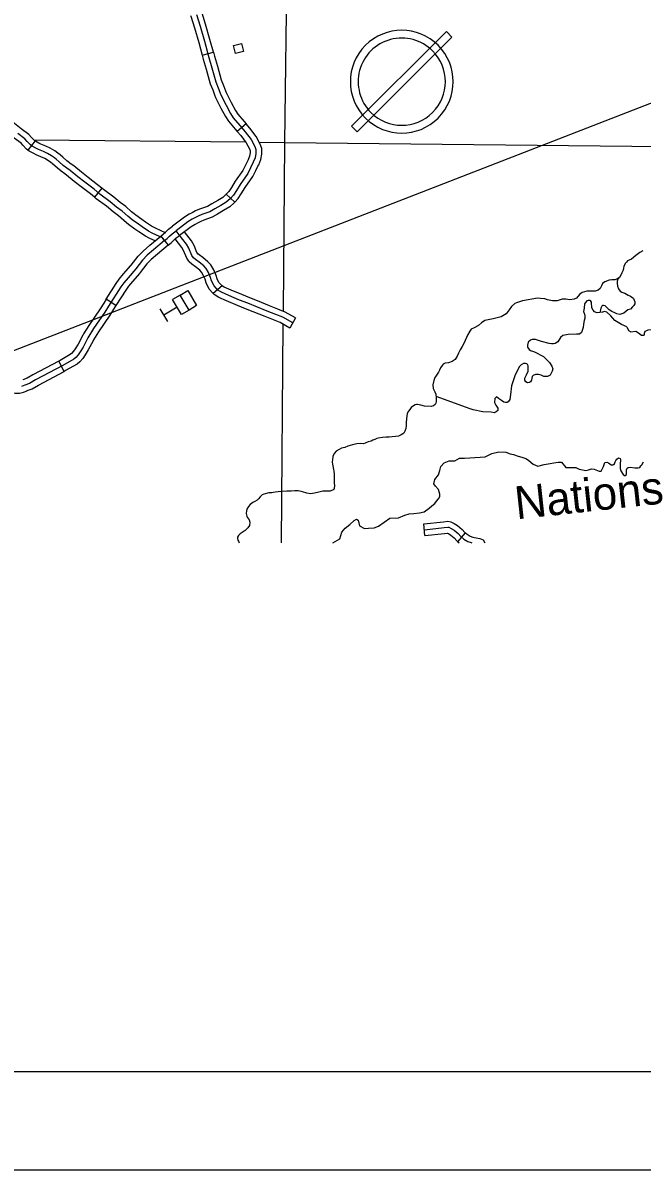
# Model space of a CAD drawing. Extents: x 61396 to 64680, y 55472 to 57605.
# Drawn here: x 62177.9 to 62426.4, y 55472.1 to 55932.3 of the extents above; entities that cross this region are included whole.
import ezdxf

# ---------------------------------------------------------------- set-up
doc = ezdxf.new("R2010")
doc.units = 0
for name, color, linetype in [('31', 7, 'Continuous'), ('32', 7, 'Continuous'), ('35', 7, 'Continuous'), ('45', 7, 'Continuous'), ('5', 7, 'Continuous'), ('56', 7, 'Continuous'), ('57', 7, 'Continuous'), ('Default', 7, 'Continuous'), ('R_No Plot', 7, 'Continuous')]:
    doc.layers.add(name, color=color, linetype=linetype)

msp = doc.modelspace()

# ---------------------------------------------------------------- linework, layer by layer
at = {"layer": '31'}
for p, q in [((62249.85, 55919.35), (62254.37, 55920.6)), ((62267.47, 55891.85), (62263.92, 55888.79)), ((62259.51, 55863.54), (62263, 55860.41)), ((62233.2, 55846.77), (62236.22, 55843.19)), ((62224.76, 55831.97), (62224.76, 55831.97)), ((62215.23, 55818.91), (62211.28, 55821.44)), ((62194.48, 55792.51), (62192.29, 55796.66)), ((62179.64, 55784.79), (62179.64, 55784.79))]:
    msp.add_line(p, q, dxfattribs=at)
for points in [[(62247.51, 55935.61), (62248.99, 55931.05), (62250.73, 55925.01), (62252.56, 55918.36), (62253.69, 55914.31), (62255.28, 55908.63), (62256.26, 55906.29), (62257.35, 55903.38), (62259.45, 55899.25), (62261.24, 55895.98), (62262.33, 55894.27), (62264.93, 55891.2), (62267.15, 55888.63), (62269.49, 55885.51), (62271.01, 55882.75), (62271.43, 55881.51), (62271.43, 55879.91), (62271.08, 55878.16), (62270.38, 55876.37), (62269.29, 55874.19), (62268.16, 55871.9), (62265.09, 55867.54), (62263.57, 55865.01), (62262.4, 55863.26), (62261.04, 55861.74), (62259.52, 55860.38), (62257.27, 55859.02), (62254.89, 55857.65), (62252.91, 55856.56), (62249.68, 55855.4), (62248.24, 55854.77), (62245.83, 55853.53), (62244.11, 55852.44), (62239.36, 55848.92)], [(62245.17, 55935.33), (62245.24, 55935.01), (62246.75, 55930.36), (62248.47, 55924.37), (62249.85, 55919.35)], [(62254.37, 55920.6), (62252.98, 55925.64), (62251.24, 55931.74), (62249.78, 55936.21), (62249.77, 55936.27)], [(62254.37, 55920.6), (62254.82, 55918.98), (62255.94, 55914.94), (62257.5, 55909.4), (62258.44, 55907.15), (62259.22, 55905.06)], [(62249.85, 55919.35), (62250.3, 55917.73), (62251.43, 55913.68), (62253.06, 55907.86), (62254.08, 55905.43), (62254.83, 55903.42)], [(62254.83, 55903.42), (62255.2, 55902.43), (62257.37, 55898.16), (62259.22, 55894.79), (62260.44, 55892.88), (62263.15, 55889.67), (62263.92, 55888.79)], [(62259.22, 55905.06), (62259.49, 55904.32), (62261.52, 55900.35), (62263.26, 55897.18), (62264.22, 55895.66), (62266.71, 55892.72), (62267.47, 55891.85)], [(62263.92, 55888.79), (62265.33, 55887.16), (62267.51, 55884.24), (62268.85, 55881.8), (62269.09, 55881.12), (62269.09, 55880.14), (62268.83, 55878.82), (62268.24, 55877.32), (62268.02, 55876.88)], [(62272.21, 55874.78), (62272.53, 55875.42), (62273.34, 55877.5), (62273.78, 55879.68), (62273.78, 55881.9), (62273.16, 55883.7), (62271.46, 55886.79), (62268.98, 55890.1), (62267.47, 55891.85)], [(62268.02, 55876.88), (62267.19, 55875.23), (62266.14, 55873.1), (62263.12, 55868.82), (62261.59, 55866.26), (62260.55, 55864.7), (62259.51, 55863.54)], [(62263, 55860.41), (62264.26, 55861.82), (62265.55, 55863.75), (62267.06, 55866.26), (62270.19, 55870.7), (62271.39, 55873.15), (62272.21, 55874.78)], [(62259.51, 55863.54), (62259.38, 55863.4), (62258.12, 55862.27), (62256.08, 55861.04), (62253.75, 55859.7), (62251.94, 55858.71), (62248.81, 55857.58), (62247.23, 55856.89), (62245.83, 55856.17)], [(62263, 55860.41), (62262.7, 55860.08), (62260.93, 55858.48), (62258.46, 55856.99), (62256.04, 55855.61), (62253.88, 55854.42), (62250.54, 55853.22), (62249.24, 55852.65), (62247.98, 55852)], [(62245.83, 55856.17), (62244.66, 55855.56), (62242.78, 55854.37), (62237.94, 55850.78)], [(62247.98, 55852), (62246.99, 55851.49), (62245.44, 55850.51), (62240.78, 55847.05)], [(62221.18, 55834.99), (62221.34, 55835.18), (62224.1, 55838.71), (62226.15, 55840.8), (62228.83, 55843.09), (62233.2, 55846.77)], [(62233.2, 55846.77), (62234.26, 55847.63), (62235.1, 55848.41), (62236.29, 55849.52), (62237.94, 55850.78)], [(62234.71, 55844.98), (62235.8, 55845.86), (62236.7, 55846.7), (62237.8, 55847.73), (62239.36, 55848.92)], [(62236.22, 55843.19), (62237.34, 55844.09), (62238.3, 55844.99), (62239.32, 55845.93), (62240.78, 55847.05)], [(62234.71, 55844.98), (62230.35, 55841.31), (62227.75, 55839.09), (62225.87, 55837.17), (62223.16, 55833.7), (62220.11, 55830.09), (62218.41, 55828.06), (62217.25, 55826.4), (62212.3, 55818.68), (62210.8, 55816.33), (62206.28, 55809.7), (62203.99, 55805.91), (62202.06, 55802.28), (62200.84, 55800.36), (62200.08, 55799.17), (62199.07, 55798.07), (62198.28, 55797.36), (62193.91, 55794.86), (62182.98, 55789.09), (62180.56, 55787.68), (62178.67, 55786.92), (62177.36, 55786.4)], [(62236.22, 55843.19), (62231.86, 55839.52), (62229.35, 55837.37), (62227.63, 55835.62), (62224.98, 55832.23), (62224.76, 55831.97)], [(62211.28, 55821.44), (62215.3, 55827.71), (62216.55, 55829.49), (62218.31, 55831.6), (62221.18, 55834.99)], [(62224.76, 55831.97), (62221.9, 55828.58), (62220.28, 55826.63), (62219.19, 55825.09), (62215.23, 55818.91)], [(62211.28, 55821.44), (62210.32, 55819.94), (62208.84, 55817.62), (62204.31, 55810.97), (62202.25, 55807.57)], [(62215.23, 55818.91), (62214.27, 55817.42), (62212.76, 55815.04), (62208.25, 55808.43), (62206.26, 55805.14)], [(62202.25, 55807.57), (62201.95, 55807.07), (62200.04, 55803.46), (62198.87, 55801.62), (62198.22, 55800.6), (62197.43, 55799.74), (62196.9, 55799.28), (62192.78, 55796.91), (62192.29, 55796.66)], [(62206.26, 55805.14), (62206.03, 55804.76), (62204.09, 55801.1), (62202.82, 55799.1), (62201.94, 55797.73), (62200.72, 55796.39), (62199.65, 55795.45), (62195.04, 55792.81), (62194.48, 55792.51)], [(62192.29, 55796.66), (62181.84, 55791.14), (62179.53, 55789.79), (62177.89, 55789.13)], [(62179.64, 55784.79), (62181.6, 55785.57), (62184.11, 55787.04), (62194.48, 55792.51)], [(62162.49, 55783.79), (62163.27, 55783.81), (62167.89, 55783.94), (62172.78, 55784.05), (62174.76, 55783.75), (62176.57, 55783.79), (62178.07, 55784.16), (62179.54, 55784.74), (62179.64, 55784.79)]]:
    msp.add_lwpolyline(points, dxfattribs=at)
at = {"layer": '32'}
for p, q in [((62339.29, 55726.68), (62338.78, 55731.34)), ((62352.51, 55724.17), (62355.57, 55727.72))]:
    msp.add_line(p, q, dxfattribs=at)
for points in [[(62338.78, 55731.34), (62346.67, 55732.2), (62348.49, 55732.39), (62349.61, 55732.23), (62350.96, 55731.53), (62352.39, 55730.67), (62354.23, 55729.12), (62355.32, 55727.93), (62355.57, 55727.72)], [(62339.03, 55729.01), (62346.92, 55729.87), (62348.44, 55730.03), (62348.89, 55729.96), (62349.81, 55729.49), (62351.02, 55728.76), (62352.61, 55727.42), (62353.69, 55726.25), (62354.86, 55725.24), (62356.47, 55724.34), (62357.81, 55723.81), (62358.04, 55723.76)], [(62339.29, 55726.68), (62347.17, 55727.54), (62348.26, 55727.65), (62348.66, 55727.44), (62349.65, 55726.85), (62350.98, 55725.72), (62352.05, 55724.56), (62352.51, 55724.17)], [(62355.57, 55727.72), (62356.21, 55727.17), (62357.48, 55726.46), (62358.5, 55726.06), (62359.89, 55725.76), (62361.27, 55725.49), (62362.64, 55724.94), (62363.3, 55723.76)], [(62352.51, 55724.17), (62352.99, 55723.76)]]:
    msp.add_lwpolyline(points, dxfattribs=at)
at = {"layer": '35'}
for points in [[(62426.75, 55840.93), (62425.58, 55840.2), (62423.98, 55839.03), (62422.16, 55837.5), (62420.63, 55836.85), (62420.12, 55836.34), (62419.68, 55835.83), (62419.17, 55834.59), (62418.95, 55834), (62418.81, 55833.06), (62418.3, 55832.11), (62417.86, 55831.16), (62417.35, 55830.14), (62416.69, 55829.49), (62416.4, 55828.76), (62416.4, 55827.88), (62416.55, 55826.64), (62416.98, 55825.69), (62417.57, 55824.75), (62418.3, 55824.24), (62419.53, 55823.87), (62420.85, 55823.14), (62421.79, 55822.63), (62422.74, 55822.05), (62423.03, 55821.69), (62423.32, 55821.1), (62423.47, 55820.45), (62423.47, 55819.64), (62423.11, 55818.92), (62422.52, 55818.41), (62421.72, 55817.53), (62420.7, 55817.17), (62419.9, 55816.51), (62419.1, 55815.85), (62417.49, 55815.34), (62416.33, 55815.64), (62415.45, 55816), (62414.29, 55816.58), (62413.19, 55817.24), (62412.39, 55818.04), (62411.59, 55818.77), (62411.01, 55818.99), (62410.57, 55818.92), (62410.21, 55818.62), (62409.99, 55818.19), (62409.91, 55817.82), (62409.7, 55817.24), (62409.52, 55816.2)], [(62417.35, 55830.14), (62416.33, 55829.57), (62415.43, 55829.25), (62414.27, 55829.21), (62413.27, 55829.04), (62411.52, 55828.49), (62410.58, 55827.72), (62410.12, 55826.78), (62409.63, 55825.8), (62408.79, 55825.07), (62407.63, 55824.71), (62406.01, 55824.63), (62404.28, 55824.68), (62402.37, 55824.18), (62401.32, 55823.29), (62400.08, 55821.87), (62399.23, 55821.48), (62397.42, 55821.21), (62395.85, 55821.51), (62394.41, 55821.5), (62392.28, 55820.88), (62391.4, 55820.81), (62390.49, 55820.83), (62388.42, 55821.25), (62387.42, 55821.55), (62385.69, 55821.81), (62384.5, 55821.86), (62378.43, 55820.76), (62377.58, 55820.57), (62376.08, 55820.05), (62375.37, 55819.7), (62374.03, 55818.55), (62373.13, 55817.16), (62371.93, 55815.55), (62369.81, 55814.33), (62366.59, 55813.55), (62364.61, 55813.24), (62363.36, 55812.92), (62362.02, 55812.02), (62360.78, 55810.88), (62359, 55809.95), (62357.85, 55809.44), (62357.23, 55808.58), (62356.4, 55807.01), (62354.96, 55804.01), (62354.19, 55802.49), (62353.35, 55801.17), (62352.8, 55799.81), (62352.16, 55798.61), (62351.36, 55797.22), (62350.17, 55796.46), (62348.73, 55796), (62347.39, 55795.77), (62346.58, 55795.38), (62346.14, 55794.84), (62345.46, 55793.99), (62345.06, 55793.01), (62344.76, 55792.19), (62344.11, 55791.4), (62343.61, 55790.64), (62343.18, 55790.01), (62342.82, 55788.88), (62342.49, 55787.15), (62342.57, 55785.67), (62342.79, 55785.08), (62343.24, 55784.36), (62343.59, 55783.33), (62343.83, 55781.89), (62343.8, 55781.38), (62343.8, 55780.91), (62343.84, 55780.35), (62343.69, 55779.78), (62343.38, 55779.18), (62342.67, 55778.64), (62341.73, 55778.41), (62339.06, 55778.54), (62337.56, 55778.9), (62336.33, 55779.2), (62335.86, 55779.23), (62335.36, 55779.04), (62334.64, 55778.75), (62333.8, 55778.05), (62333.15, 55777.22), (62332.69, 55776.59), (62332.16, 55775.61), (62331.96, 55774.61), (62331.81, 55773.57), (62331.7, 55771.87), (62331.74, 55770.65), (62331.57, 55769.64), (62331.26, 55768.6), (62330.77, 55767.69), (62330.43, 55767.43), (62329.74, 55767.02), (62328.71, 55766.51), (62324.89, 55766.15), (62323.7, 55766.08), (62322.26, 55765.97), (62320.44, 55765.79)], [(62420.32, 55810.43), (62418.14, 55811.38), (62415.48, 55812.9), (62413.87, 55814.79), (62412.31, 55816.24), (62411.33, 55816.55), (62410.5, 55816.32), (62409.52, 55816.2), (62408.38, 55815.96), (62407.32, 55816.44), (62406.77, 55817.06), (62406.26, 55817.97), (62406.26, 55818.6), (62406.18, 55819.66), (62406.1, 55820.29), (62405.91, 55820.68), (62405.47, 55820.91), (62404.81, 55820.95), (62404.26, 55820.8), (62403.67, 55820.13), (62403.35, 55819.58), (62403.12, 55817.81), (62402.92, 55816.51), (62403.27, 55815.53), (62403.43, 55814.79), (62403.43, 55813.84), (62403.16, 55812.9), (62402.88, 55811.52), (62402.72, 55810.11), (62402.09, 55808.11), (62401.27, 55807.48), (62400.05, 55807.44), (62396.75, 55807.32), (62394.63, 55806.85), (62393.69, 55806.06), (62392.63, 55804.41), (62391.56, 55803.67), (62390.82, 55803.55), (62390.03, 55803.55), (62389.09, 55803.67), (62386.02, 55804.53), (62383.71, 55805.32), (62382.29, 55805.32), (62381.66, 55805.08), (62380.68, 55804.18), (62380.37, 55803.08), (62380.48, 55802.21), (62381.07, 55801.23), (62381.66, 55800.92), (62383.2, 55800.29), (62386.85, 55798.52), (62388.26, 55797.15), (62389.25, 55796.12), (62390.23, 55794.63), (62390.62, 55793.49), (62390.39, 55792.59), (62389.52, 55790.94), (62388.46, 55790.51), (62387.01, 55790.51), (62385.87, 55790.94), (62384.85, 55791.25), (62383.63, 55791.21), (62382.76, 55790.9), (62382.37, 55790.47), (62382.21, 55789.8), (62382.02, 55788.93), (62381.7, 55788.31), (62381.23, 55787.99), (62380.48, 55787.91), (62379.78, 55788.31), (62379.38, 55789.01), (62379.42, 55789.76), (62380.01, 55791.17), (62380.64, 55792.63), (62380.68, 55793.65), (62380.68, 55794.36), (62380.68, 55794.75), (62380.44, 55795.34), (62380.17, 55795.57), (62379.7, 55795.65), (62378.79, 55795.61), (62377.89, 55795.18), (62377.14, 55794.4), (62375.38, 55790.78), (62373.96, 55786.73), (62373.61, 55783.24), (62373.33, 55781.27), (62372.74, 55780.25), (62372.27, 55780.05), (62371.56, 55780.05), (62370.94, 55780.21), (62369.99, 55780.8), (62368.78, 55781.7), (62368.03, 55782.25), (62367.6, 55781.94), (62367.28, 55781.67), (62367.24, 55780.02), (62367.71, 55779.03), (62368.58, 55777.78), (62368.54, 55776.83), (62367.91, 55776.24)], [(62420.32, 55810.43), (62420.96, 55808.98), (62421.91, 55808.39), (62423.99, 55808.6), (62424.95, 55808.02), (62426.22, 55807.01), (62427.13, 55807.01), (62427.34, 55807.22), (62427.45, 55807.91), (62427.66, 55808.6), (62428.3, 55808.92), (62428.93, 55809.19), (62430.1, 55809.3), (62431.11, 55809.42)], [(62367.91, 55776.24), (62367.12, 55775.93), (62365.79, 55776.09), (62362.57, 55776.24), (62358.68, 55777.03), (62357.38, 55777.46), (62343.73, 55782.48)], [(62320.44, 55765.79), (62319.94, 55765.54), (62319.16, 55765.21), (62318.35, 55764.92), (62317.67, 55764.57), (62316.54, 55764.21), (62315.32, 55763.76), (62314.6, 55763.5), (62313.51, 55763.52), (62311.88, 55763.41), (62310.13, 55763.02), (62308.38, 55762.5), (62307.16, 55762.04), (62305.72, 55761.68), (62304.81, 55761.23), (62303.69, 55760.53), (62303.01, 55759.74), (62302.36, 55758.54), (62302.31, 55758.23), (62302.16, 55757.19), (62302.08, 55756.12), (62302.15, 55755.27), (62302.25, 55754.58), (62302.51, 55753.14), (62302.64, 55752.67), (62302.85, 55751.14), (62302.8, 55749.88), (62302.81, 55748.56), (62302.79, 55747.68), (62302.95, 55746.68), (62302.84, 55745.58), (62302.65, 55745.11), (62301.28, 55744.53), (62299.96, 55744.51), (62298.3, 55744.4), (62296.65, 55744.13), (62294.99, 55743.68), (62293.33, 55743.41), (62291.79, 55743.61), (62290.16, 55744.19), (62288.33, 55744.61), (62287.05, 55744.66), (62285.58, 55744.52), (62283.79, 55744.47), (62282, 55744.36), (62280.41, 55744.15), (62279.15, 55744.05), (62277.75, 55743.84), (62276.62, 55743.74), (62274.65, 55743.28), (62273.99, 55743.05), (62273.12, 55742.26), (62272.41, 55741.4), (62271.91, 55740.9), (62270.98, 55740.29), (62270.2, 55739.94), (62269.11, 55739.08), (62268.46, 55738.38), (62267.78, 55737.21), (62267.63, 55736.55), (62267.55, 55735.45), (62267.71, 55734.38), (62267.91, 55733.98), (62268.29, 55733.48), (62268.7, 55732.92), (62268.93, 55732.04), (62268.78, 55730.69), (62268.17, 55729.71), (62267.08, 55728.73), (62265.96, 55727.84), (62265.15, 55727.33), (62264.47, 55726.72), (62264.07, 55726), (62263.98, 55725.49), (62264.11, 55724.8), (62264.4, 55724.4), (62264.7, 55723.76)], [(62302.32, 55723.76), (62305.08, 55725.29), (62305.89, 55728.08), (62307.23, 55729.59), (62309.16, 55731.14), (62310.92, 55732.68), (62311.78, 55733.29), (62312.43, 55732.86), (62313.03, 55730.58), (62314.96, 55729.46), (62316.56, 55729.59), (62318.83, 55729.76), (62320.6, 55730.49), (62325.24, 55733.63), (62328.63, 55733.83), (62331.13, 55734.88), (62332.98, 55735.43), (62334.87, 55735.56), (62337.06, 55735.78), (62339, 55736.17), (62340.97, 55737.67), (62342.09, 55738.57), (62343.21, 55739.57), (62343.86, 55740.51), (62344.73, 55741.34), (62345.28, 55742.29), (62345.3, 55743.32), (62344.72, 55745.11), (62343.46, 55746.47), (62342.82, 55747.38), (62343.3, 55749.14), (62344.7, 55751.04), (62345.31, 55752.8), (62345.63, 55754.34), (62347.03, 55755.87), (62348.93, 55756.67), (62351.29, 55756.58), (62353.1, 55757.66), (62355.2, 55757.7), (62357.27, 55757.87), (62363.46, 55758.22), (62366.12, 55759.55), (62368.9, 55760.3)], [(62368.9, 55760.3), (62371.75, 55760.17), (62373.51, 55759.47), (62374.87, 55759.14), (62376.69, 55758.53), (62378.11, 55758.07), (62379.8, 55757.53), (62380.84, 55756.85), (62381.92, 55755.98), (62382.71, 55755.26), (62384.63, 55754.53), (62387.07, 55755.15), (62389.48, 55755.62), (62390.95, 55755.82), (62392.7, 55756.09), (62394.02, 55756.04), (62395.85, 55753.9), (62399.79, 55753.9), (62401.16, 55753.26), (62403.9, 55752.78), (62404.93, 55753.09), (62406.19, 55753.36), (62407.17, 55753.23), (62408.52, 55752.69), (62409.19, 55752.46), (62410.04, 55752.51), (62410.98, 55754.39), (62411.52, 55755.91), (62412.32, 55756.09), (62412.95, 55755.82)], [(62412.95, 55755.82), (62414.04, 55755), (62414.63, 55755.04), (62415.37, 55755.39), (62415.67, 55756.23), (62415.87, 55756.83), (62416.36, 55757.32), (62416.96, 55757.82), (62417.6, 55757.52), (62417.8, 55757.02), (62417.6, 55755.29), (62417.6, 55753.51), (62417.95, 55752.62), (62418.79, 55751.19), (62419.33, 55750.74), (62419.58, 55750.74), (62420.12, 55751.09), (62420.22, 55751.83), (62420.22, 55752.37), (62420.22, 55753.07), (62420.42, 55753.71), (62420.81, 55753.91), (62421.76, 55754.15), (62423.49, 55753.76), (62424.87, 55753.76), (62425.57, 55754.01), (62425.91, 55754.6), (62426.31, 55755.04), (62427, 55756.23)]]:
    msp.add_lwpolyline(points, dxfattribs=at)
at = {"layer": '45'}
for p, q in [((62182.74, 55884.97), (62179.86, 55881.27)), ((62209.61, 55865.94), (62206.58, 55862.36)), ((62257.81, 55826.8), (62254.28, 55823.72)), ((62287.33, 55813.98), (62285.02, 55809.9))]:
    msp.add_line(p, q, dxfattribs=at)
for points in [[(62182.74, 55884.97), (62182.51, 55885.15), (62181.31, 55886.38), (62180.32, 55887.52), (62177.24, 55889.79), (62172.46, 55893.51), (62170.12, 55895.44)], [(62179.86, 55881.27), (62179.37, 55881.65), (62177.87, 55883.2), (62177.13, 55884.04), (62174.41, 55886.05), (62169.53, 55889.85), (62167.14, 55891.82)], [(62234.71, 55844.98), (62234.02, 55845.88), (62233.64, 55846.23), (62232.74, 55846.67), (62229.81, 55847.93), (62228.26, 55848.73), (62225.77, 55850.43), (62224.22, 55851.5), (62221.76, 55853.28), (62219.98, 55854.79), (62217.72, 55856.81), (62215.5, 55858.36), (62212.89, 55860.57), (62208.76, 55863.59), (62206.43, 55865.57), (62202.7, 55868.38), (62199.89, 55870.56), (62196.87, 55873.1), (62195.53, 55874.05), (62194.1, 55875.12), (62192.4, 55876.62), (62191.29, 55877.58), (62190.53, 55878.21), (62189.42, 55878.96), (62187.76, 55879.95), (62186.09, 55880.75), (62184.11, 55881.58), (62183.28, 55881.97), (62181.65, 55882.85), (62180.94, 55883.4), (62179.59, 55884.79), (62178.72, 55885.78), (62175.83, 55887.92)], [(62196.54, 55876.22), (62195.58, 55876.94), (62193.93, 55878.39), (62192.8, 55879.36), (62191.95, 55880.08), (62190.68, 55880.94), (62188.86, 55882.02), (62187.05, 55882.89), (62185.07, 55883.72), (62184.34, 55884.07), (62182.94, 55884.82), (62182.74, 55884.97)], [(62193.73, 55872.47), (62192.62, 55873.3), (62190.86, 55874.86), (62189.77, 55875.79), (62189.12, 55876.34), (62188.16, 55876.98), (62186.65, 55877.88), (62185.14, 55878.61), (62183.15, 55879.44), (62182.22, 55879.88), (62180.37, 55880.87), (62179.86, 55881.27)], [(62209.61, 55865.94), (62207.89, 55867.4), (62204.12, 55870.24), (62201.36, 55872.39), (62198.31, 55874.95), (62196.91, 55875.94), (62196.54, 55876.22)], [(62206.58, 55862.36), (62204.96, 55863.74), (62201.28, 55866.52), (62198.41, 55868.74), (62195.44, 55871.24), (62194.15, 55872.15), (62193.73, 55872.47)], [(62222.53, 55855.7), (62221.52, 55856.56), (62219.18, 55858.65), (62216.93, 55860.22), (62214.34, 55862.42), (62210.21, 55865.43), (62209.61, 55865.94)], [(62219.5, 55852.12), (62218.44, 55853.02), (62216.26, 55854.97), (62214.07, 55856.5), (62211.43, 55858.73), (62207.31, 55861.74), (62206.58, 55862.36)], [(62234.9, 55848.23), (62233.71, 55848.8), (62230.81, 55850.05), (62229.46, 55850.74), (62227.09, 55852.36), (62225.58, 55853.41), (62223.21, 55855.13), (62222.53, 55855.7)], [(62230.96, 55844.88), (62228.81, 55845.81), (62227.06, 55846.71), (62224.44, 55848.5), (62222.87, 55849.59), (62220.32, 55851.44), (62219.5, 55852.12)], [(62286.17, 55811.94), (62282.16, 55814.21), (62279.4, 55815.32), (62275.99, 55816.67), (62268.17, 55819.82), (62264.88, 55821.14), (62260.51, 55822.98), (62257.65, 55824.26), (62256.14, 55825.15), (62254.63, 55826.89), (62253.61, 55828.84), (62253.24, 55830.23), (62252.38, 55832.21), (62251.44, 55833.79), (62250.46, 55834.8), (62248.66, 55836.34), (62247.2, 55837.39), (62246.41, 55838.11), (62245.69, 55839.04), (62244.49, 55841.97), (62243.59, 55843.55), (62240.67, 55847.26), (62239.36, 55848.92)], [(62248.24, 55839.57), (62247.75, 55840.22), (62246.6, 55843), (62245.54, 55844.86), (62242.7, 55848.47)], [(62244.5, 55836.74), (62243.64, 55837.87), (62242.38, 55840.94), (62241.64, 55842.23), (62238.98, 55845.62)], [(62257.81, 55826.8), (62256.58, 55828.21), (62255.81, 55829.69), (62255.46, 55831), (62254.47, 55833.28), (62253.31, 55835.22), (62252.07, 55836.51), (62250.11, 55838.19), (62248.67, 55839.22), (62248.14, 55839.7), (62248.24, 55839.57)], [(62254.28, 55823.72), (62252.68, 55825.56), (62251.42, 55827.98), (62251.02, 55829.45), (62250.28, 55831.14), (62249.56, 55832.36), (62248.85, 55833.1), (62247.21, 55834.5), (62245.72, 55835.57), (62244.67, 55836.51), (62244.5, 55836.74)], [(62270.25, 55816.46), (62267.29, 55817.65), (62263.99, 55818.97), (62259.58, 55820.83), (62256.58, 55822.17), (62254.62, 55823.32), (62254.28, 55823.72)], [(62272, 55820.81), (62269.04, 55822), (62265.77, 55823.31), (62261.44, 55825.13), (62258.73, 55826.35), (62257.66, 55826.97), (62257.81, 55826.8)], [(62287.33, 55813.98), (62283.18, 55816.32), (62280.27, 55817.5), (62276.85, 55818.85), (62272, 55820.81)], [(62285.02, 55809.9), (62281.14, 55812.09), (62278.53, 55813.15), (62275.12, 55814.49), (62270.25, 55816.46)]]:
    msp.add_lwpolyline(points, dxfattribs=at)
at = {"layer": '5'}
for points in [[(62283.8, 55957.14), (62282.84, 55884.38)], [(62182.35, 55885.42), (62267.35, 55884.54)], [(62272.73, 55884.48), (62282.84, 55884.38)], [(62282.84, 55884.38), (62282.31, 55816.68)], [(62282.84, 55884.38), (62447.66, 55882.61)], [(62282.26, 55811.46), (62281.57, 55723.76)]]:
    msp.add_lwpolyline(points, dxfattribs=at)
at = {"layer": '56'}
msp.add_lwpolyline([(62263.24, 55920.04), (62262.47, 55923.2), (62265.64, 55923.97), (62266.41, 55920.81)], close=True, dxfattribs=at)
at = {"layer": '57'}
for p, q in [((62347.86, 55928.83), (62309.85, 55890.82)), ((62312.06, 55888.61), (62350.06, 55926.62)), ((62350.06, 55926.62), (62347.86, 55928.83)), ((62309.85, 55890.82), (62312.06, 55888.61)), ((62241.01, 55823.15), (62237.99, 55821.35)), ((62244.61, 55817.12), (62241.01, 55823.15)), ((62232.91, 55817.67), (62235.97, 55812.54)), ((62239.79, 55818.33), (62234.42, 55815.13))]:
    msp.add_line(p, q, dxfattribs=at)
for points in [[(62241.01, 55823.15), (62244.03, 55824.96), (62247.63, 55818.92), (62244.61, 55817.12)], [(62244.61, 55817.12), (62241.59, 55815.32), (62237.99, 55821.35)]]:
    msp.add_lwpolyline(points, dxfattribs=at)
for radius, start, end in [(20.63, 45, 225), (17.5, 45, 225.0001), (20.63, 225, 45), (17.5, 225.0001, 45)]:
    msp.add_arc((62329.96, 55908.72), radius, start, end, dxfattribs=at)
at = {"layer": 'Default'}
for p, q in [((62046.64, 55751.5), (62762.7, 56029.16)), ((64633.61, 55511.58), (61471.8, 55511.58))]:
    msp.add_line(p, q, dxfattribs=at)
at = {"layer": 'R_No Plot'}
msp.add_lwpolyline([(61396.28, 57605.48), (64679.67, 57605.48), (64679.67, 55472.15), (61396.28, 55472.15)], close=True, dxfattribs=at)

# ---------------------------------------------------------------- texts
at = {"layer": '35'}
msp.add_text('Nations', height=13.2, rotation=6.2044, dxfattribs=at).set_placement((62376.01, 55733.14))

doc.saveas('drawing.dxf')
